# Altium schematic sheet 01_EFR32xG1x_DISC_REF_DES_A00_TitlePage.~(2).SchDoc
size 420 x 297 mm
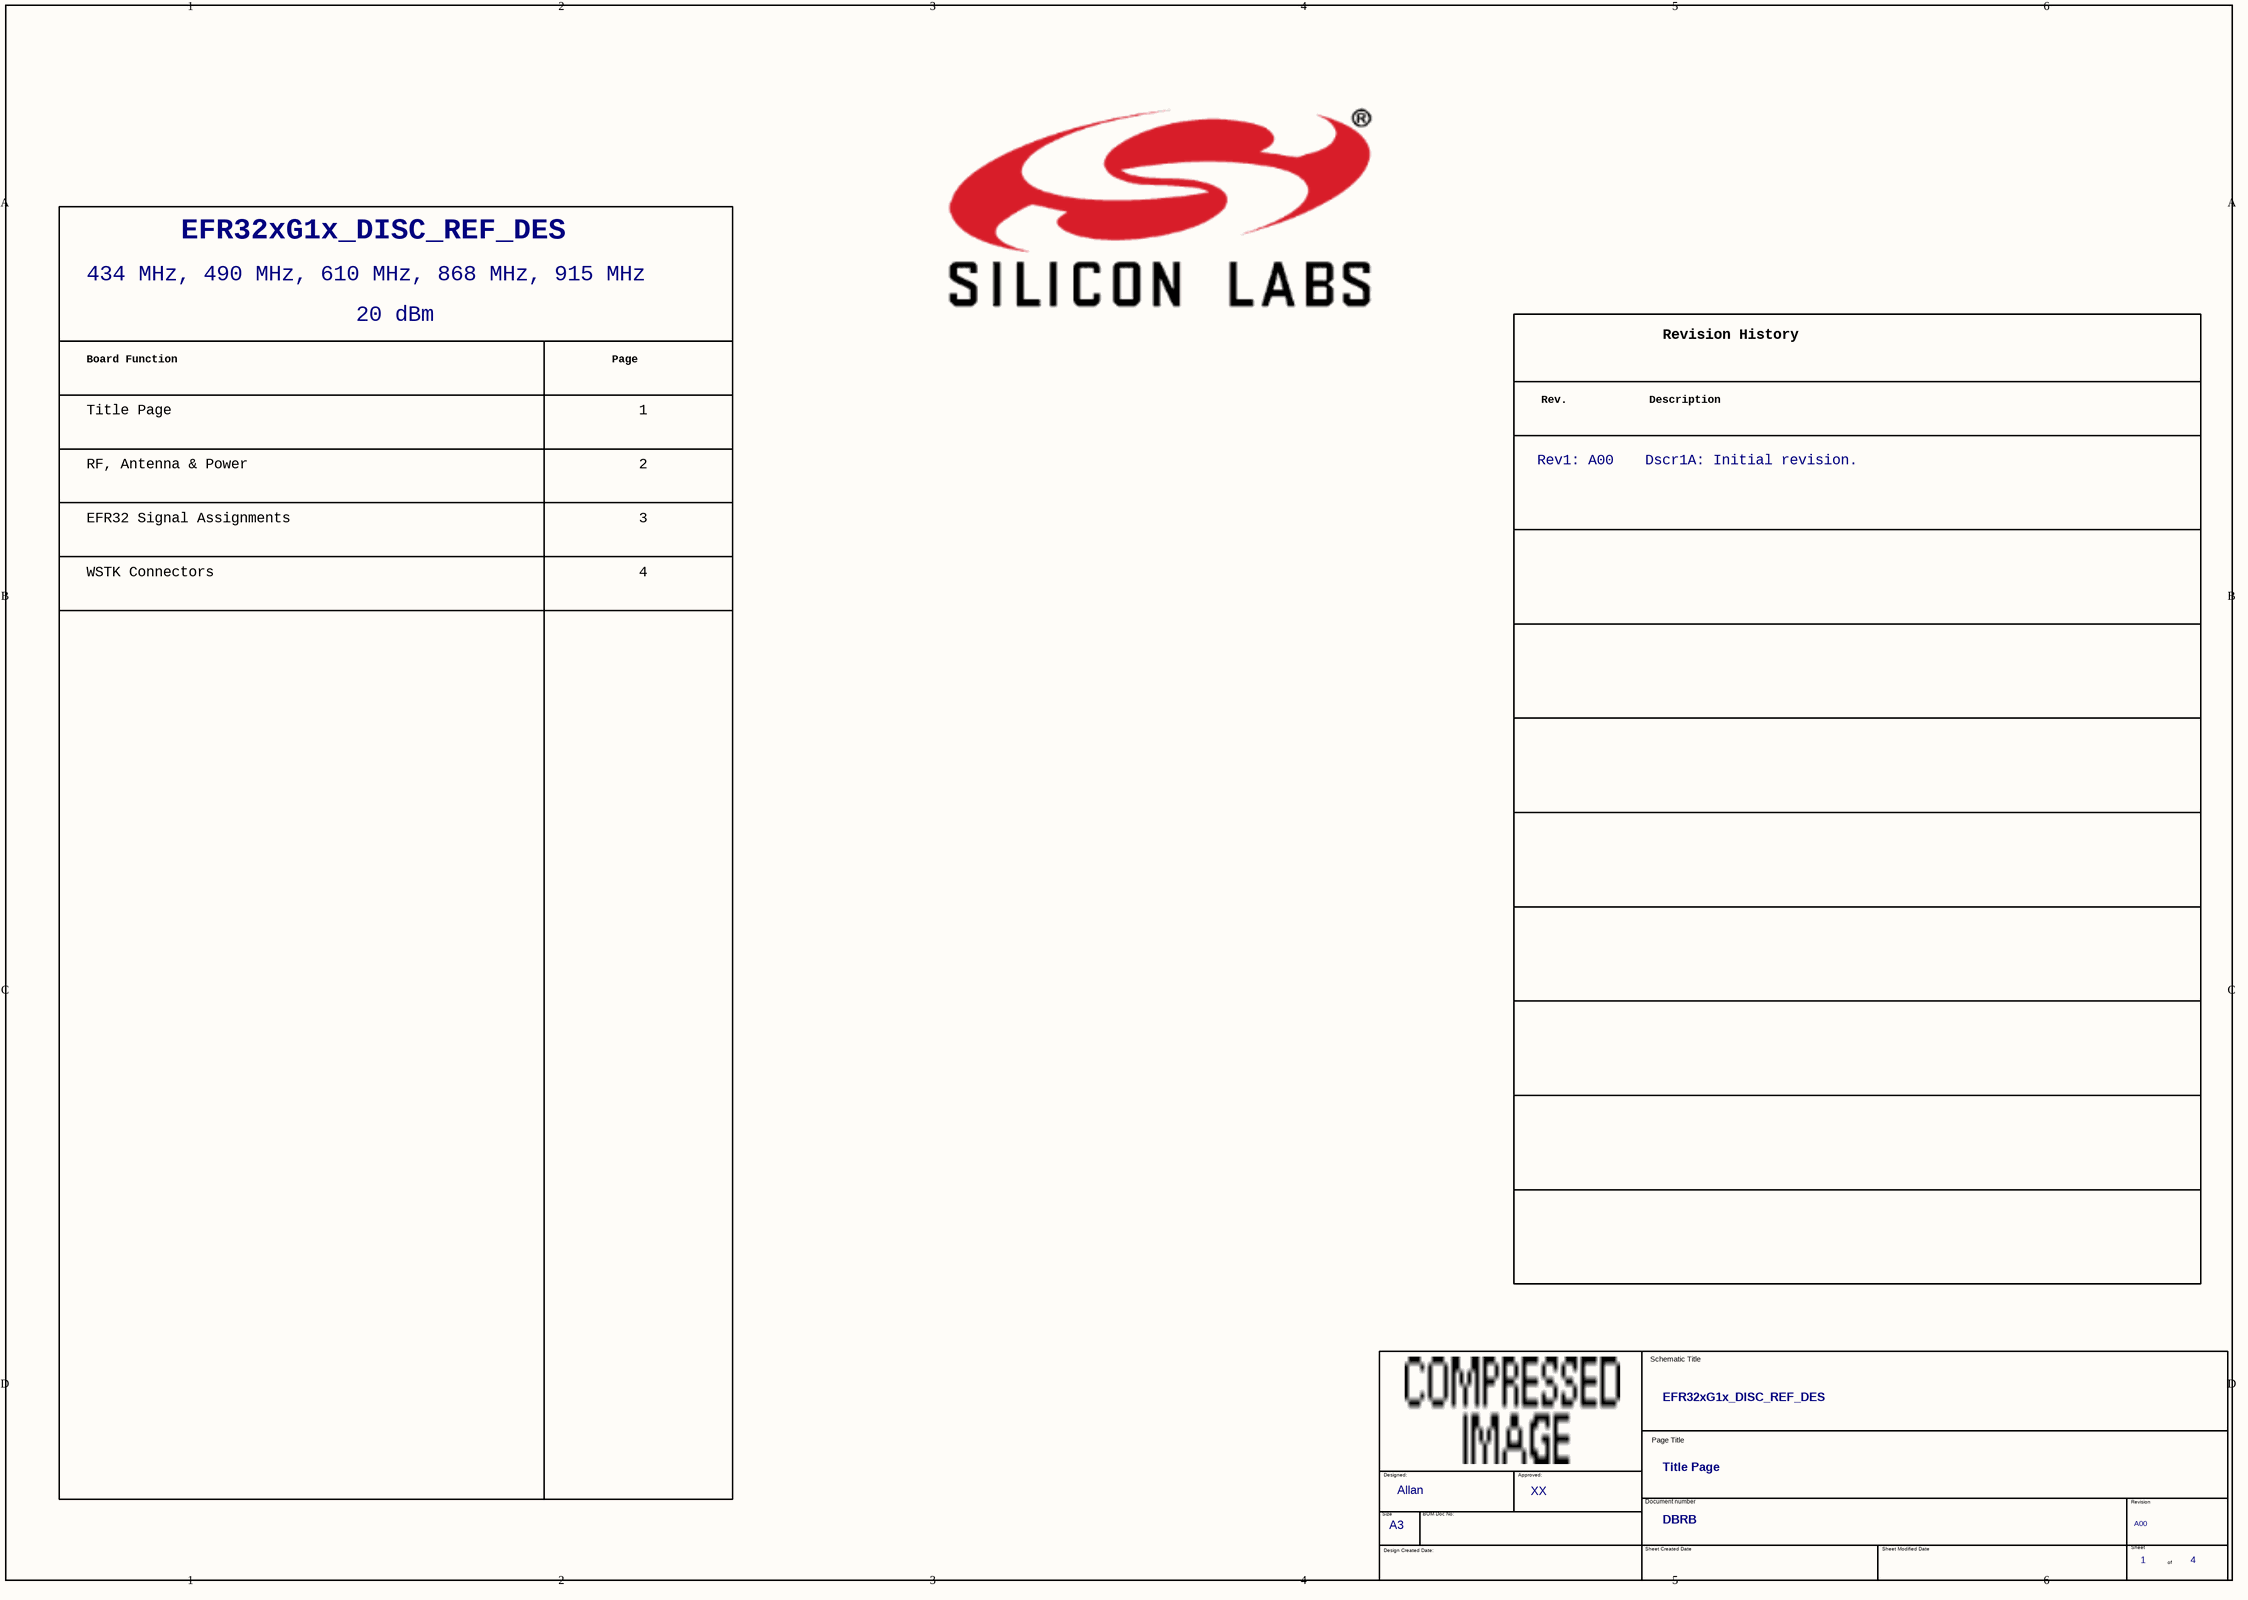
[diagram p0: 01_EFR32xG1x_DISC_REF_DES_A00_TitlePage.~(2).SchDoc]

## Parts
(Parts that share a designator on the sheet are numbered #1, #2 ... from top to bottom, then left to right.)
*#1  Header A: EFR32xG1x_DISC_REF_DES  (hidden comment: Toc_Header)  (graphical)
*#2  Dscr1A: Initial revision.  Rev1: A00  (hidden comment: Rev_History)  (graphical)
*#3  OrgAddr2: XX  OrgAddr1: Allan  Page Count: 4  Page Number: 1  Doc: DBRB  Title: EFR32xG1x_DISC_REF_DES  RevCode: A00  Page Size: A3  Page Title: Title Page  (hidden comment: TitleBlock_EnergyMicro_A3)  (graphical)

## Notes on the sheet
- 434 MHz, 490 MHz, 610 MHz, 868 MHz, 915 MHz
- 20 dBm
- Board Function
- Page
- Title Page
- 1
- EFR32 Signal Assignments
- RF, Antenna & Power
- 2
- 3
- WSTK Connectors
- 4

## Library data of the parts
*#1 = Toc_Header: Doc: BRD4259A; Page Count: 5; Page Number: 1; OrgName: Silicon Labs; RevCode: A01
*#2 = Rev_History: Doc: BRD4259A; RevCode: A01; Title: EFR32FG14 2.4 GHz / 434 MHz 10 dBm Radio Board; OrgAddr2: JNO; OrgAddr1: JSH; OrgName: Silicon Labs; Page Number: 1; Page Count: 5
